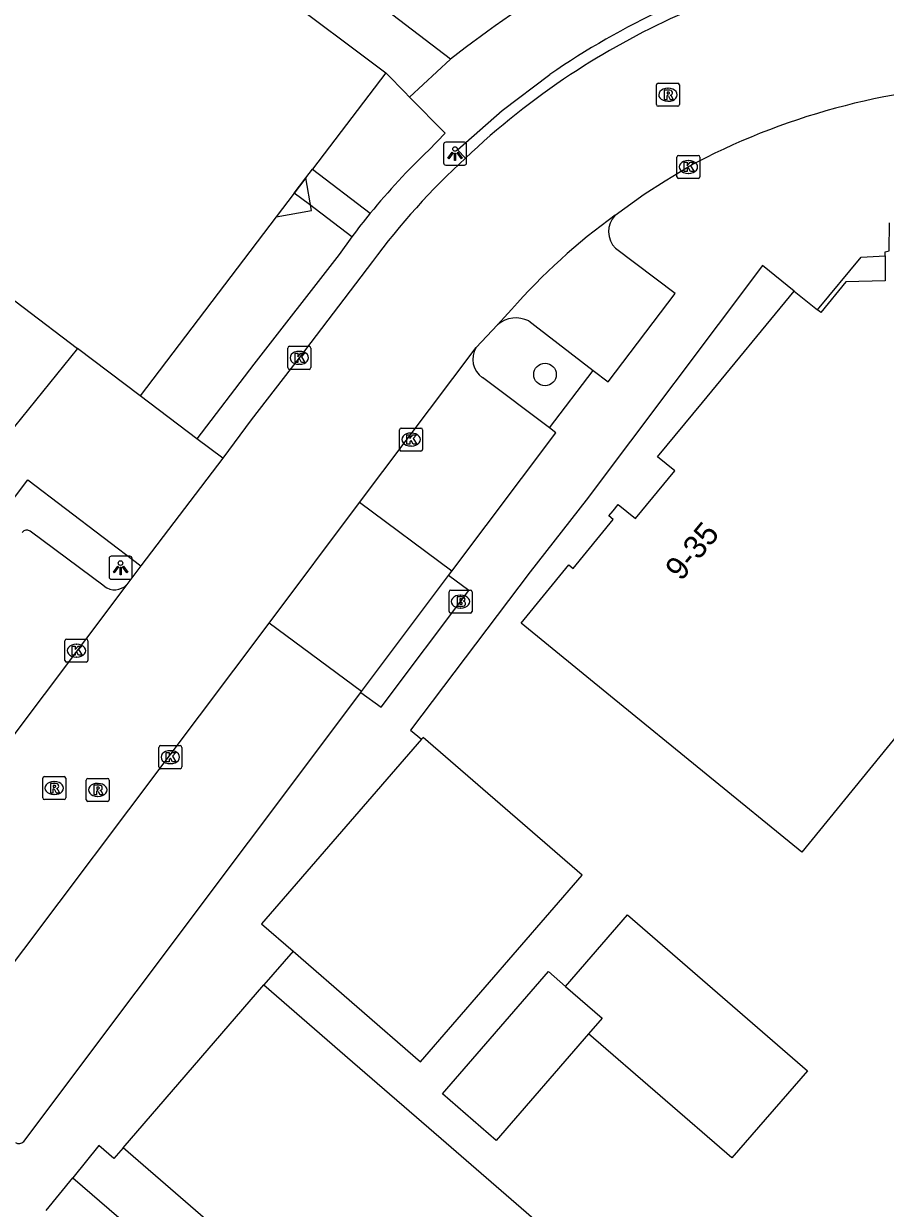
# Model space of a CAD drawing. Extents: x 161882 to 162509, y 381687 to 382379.
# Drawn here: x 162000 to 162037.4, y 382200.8 to 382252.2 of the extents above; entities that cross this region are included whole.
import ezdxf

# ---------------------------------------------------------------- set-up
doc = ezdxf.new("R2010")
doc.units = 0
for name, color, linetype in [('IMGEO_Boom', 7, 'Continuous'), ('IMGEO_Brandkraan', 7, 'Continuous'), ('IMGEO_Kolk', 7, 'Continuous'), ('IMGEO_Lichtpunt', 7, 'Continuous'), ('IMGEO_Pand', 7, 'Continuous'), ('IMGEO_Pand_nummerreeks', 7, 'Continuous'), ('IMGEO_Pand_overbouw', 7, 'Continuous'), ('IMGEO_Parkeervlak_open', 7, 'Continuous'), ('IMGEO_Rijbaan_lokaal_open', 7, 'Continuous'), ('IMGEO_Rioolput', 7, 'Continuous'), ('IMGEO_Voetpad_open', 7, 'Continuous')]:
    doc.layers.add(name, color=color, linetype=linetype)

msp = doc.modelspace()

# ---------------------------------------------------------------- linework, layer by layer
at = {"layer": 'IMGEO_Boom'}
msp.add_circle((162022.629, 382236.986), 0.489, dxfattribs=at)
at = {"layer": 'IMGEO_Brandkraan'}
for p, q in [((162018.466, 382226.715), (162018.466, 382227.567)), ((162018.541, 382227.641), (162019.393, 382227.641)), ((162018.954, 382227.421), (162018.979, 382227.421)), ((162019.467, 382227.567), (162019.467, 382226.715)), ((162018.977, 382226.861), (162018.952, 382226.861)), ((162019.393, 382226.641), (162018.541, 382226.641))]:
    msp.add_line(p, q, dxfattribs=at)
for points in [[(162018.466, 382226.715), (162018.466, 382227.567)], [(162018.541, 382227.641), (162019.393, 382227.641)], [(162018.814, 382227.341), (162018.814, 382226.941), (162019.027, 382226.941)], [(162019.045, 382227.341), (162018.814, 382227.341)], [(162018.993, 382227.26), (162018.939, 382227.26), (162018.939, 382227.184)], [(162018.939, 382227.184), (162018.992, 382227.184)], [(162019.467, 382227.567), (162019.467, 382226.715)], [(162019.001, 382227.108), (162018.939, 382227.108), (162018.939, 382227.027)], [(162018.939, 382227.027), (162019.001, 382227.027)], [(162019.393, 382226.641), (162018.541, 382226.641)]]:
    msp.add_lwpolyline(points, dxfattribs=at)
for centre, radius, start, end in [((162018.543, 382227.565), 0.0765, 91.552, 178.448), ((162018.543, 382227.565), 0.0765, 91.552, 178.448), ((162018.994, 382227.222), 0.0379, 267.8285, 90.9355), ((162019.049, 382227.196), 0.145, 59.4692, 91.5367), ((162019.074, 382227.243), 0.0922, 285.5137, 58.1501), ((162019.391, 382227.565), 0.0765, 1.552, 88.448), ((162019.391, 382227.565), 0.0765, 1.552, 88.448), ((162018.543, 382226.717), 0.0765, 181.552, 268.448), ((162018.543, 382226.717), 0.0765, 181.552, 268.448), ((162019.002, 382227.067), 0.0404, 269.8759, 90.5077), ((162019.033, 382227.192), 0.251, 268.6676, 293.5347), ((162019.079, 382227.051), 0.105, 301.3115, 78.989), ((162019.391, 382226.717), 0.0765, 271.552, 358.448), ((162019.391, 382226.717), 0.0765, 271.552, 358.448)]:
    msp.add_arc(centre, radius, start, end, dxfattribs=at)
for centre, major_axis, ratio, start_param, end_param in [((162018.953, 382227.141), (-0.387, 0.002), 0.722429, 4.712389, 7.853982), ((162018.978, 382227.141), (-0.39, 0.002), 0.717154, 1.570796, 4.712389)]:
    msp.add_ellipse(centre, major_axis=major_axis, ratio=ratio, start_param=start_param, end_param=end_param, dxfattribs=at)
at = {"layer": 'IMGEO_Kolk'}
for p, q in [((162028.346, 382245.566), (162028.346, 382246.418)), ((162028.421, 382246.492), (162029.273, 382246.492)), ((162028.834, 382246.272), (162028.859, 382246.272)), ((162029.347, 382246.418), (162029.347, 382245.566)), ((162028.857, 382245.712), (162028.832, 382245.712)), ((162029.273, 382245.492), (162028.421, 382245.492)), ((162011.473, 382237.287), (162011.473, 382238.139)), ((162011.548, 382238.213), (162012.4, 382238.213)), ((162011.961, 382237.993), (162011.986, 382237.993)), ((162012.474, 382238.139), (162012.474, 382237.287)), ((162012.4, 382237.213), (162011.548, 382237.213)), ((162011.984, 382237.433), (162011.959, 382237.433)), ((162016.322, 382233.743), (162016.322, 382234.595)), ((162016.397, 382234.669), (162017.249, 382234.669)), ((162016.81, 382234.449), (162016.835, 382234.449)), ((162017.323, 382234.595), (162017.323, 382233.743)), ((162016.833, 382233.889), (162016.808, 382233.889)), ((162017.249, 382233.669), (162016.397, 382233.669)), ((162001.809, 382224.589), (162001.809, 382225.441)), ((162001.884, 382225.515), (162002.736, 382225.515)), ((162002.297, 382225.295), (162002.322, 382225.295)), ((162002.81, 382225.441), (162002.81, 382224.589)), ((162002.32, 382224.735), (162002.295, 382224.735)), ((162002.736, 382224.515), (162001.884, 382224.515)), ((162005.882, 382219.968), (162005.882, 382220.82)), ((162005.957, 382220.894), (162006.809, 382220.894)), ((162006.37, 382220.674), (162006.395, 382220.674)), ((162006.883, 382220.82), (162006.883, 382219.968)), ((162006.393, 382220.114), (162006.368, 382220.114)), ((162006.809, 382219.894), (162005.957, 382219.894))]:
    msp.add_line(p, q, dxfattribs=at)
for points in [[(162028.346, 382245.566), (162028.346, 382246.418)], [(162028.421, 382246.492), (162029.273, 382246.492)], [(162028.667, 382246.192), (162028.79, 382246.192), (162028.79, 382246.041), (162028.92, 382246.192), (162029.084, 382246.192), (162028.938, 382246.041), (162029.091, 382245.792), (162028.939, 382245.792), (162028.854, 382245.956), (162028.79, 382245.889), (162028.79, 382245.792), (162028.667, 382245.792), (162028.667, 382246.192)], [(162029.347, 382246.418), (162029.347, 382245.566)], [(162029.273, 382245.492), (162028.421, 382245.492)], [(162011.473, 382237.287), (162011.473, 382238.139)], [(162011.548, 382238.213), (162012.4, 382238.213)], [(162012.474, 382238.139), (162012.474, 382237.287)], [(162011.794, 382237.913), (162011.917, 382237.913), (162011.917, 382237.762), (162012.047, 382237.913), (162012.211, 382237.913), (162012.065, 382237.762), (162012.218, 382237.513), (162012.066, 382237.513), (162011.981, 382237.677), (162011.917, 382237.61), (162011.917, 382237.513), (162011.794, 382237.513), (162011.794, 382237.913)], [(162012.4, 382237.213), (162011.548, 382237.213)], [(162016.322, 382233.743), (162016.322, 382234.595)], [(162016.397, 382234.669), (162017.249, 382234.669)], [(162017.323, 382234.595), (162017.323, 382233.743)], [(162016.643, 382234.369), (162016.766, 382234.369), (162016.766, 382234.218), (162016.896, 382234.369), (162017.06, 382234.369), (162016.914, 382234.218), (162017.067, 382233.969), (162016.915, 382233.969), (162016.83, 382234.133), (162016.766, 382234.066), (162016.766, 382233.969), (162016.643, 382233.969), (162016.643, 382234.369)], [(162017.249, 382233.669), (162016.397, 382233.669)], [(162001.809, 382224.589), (162001.809, 382225.441)], [(162001.884, 382225.515), (162002.736, 382225.515)], [(162002.13, 382225.215), (162002.253, 382225.215), (162002.253, 382225.064), (162002.383, 382225.215), (162002.547, 382225.215), (162002.401, 382225.064), (162002.554, 382224.815), (162002.402, 382224.815), (162002.317, 382224.979), (162002.253, 382224.912), (162002.253, 382224.815), (162002.13, 382224.815), (162002.13, 382225.215)], [(162002.81, 382225.441), (162002.81, 382224.589)], [(162002.736, 382224.515), (162001.884, 382224.515)], [(162005.882, 382219.968), (162005.882, 382220.82)], [(162005.957, 382220.894), (162006.809, 382220.894)], [(162006.203, 382220.594), (162006.326, 382220.594), (162006.326, 382220.443), (162006.456, 382220.594), (162006.62, 382220.594), (162006.474, 382220.443), (162006.627, 382220.194), (162006.475, 382220.194), (162006.39, 382220.358), (162006.326, 382220.291), (162006.326, 382220.194), (162006.203, 382220.194), (162006.203, 382220.594)], [(162006.883, 382220.82), (162006.883, 382219.968)], [(162006.809, 382219.894), (162005.957, 382219.894)]]:
    msp.add_lwpolyline(points, dxfattribs=at)
for centre, start, end in [((162028.423, 382246.416), 91.552, 178.448), ((162028.423, 382246.416), 91.552, 178.448), ((162029.271, 382246.416), 1.552, 88.448), ((162029.271, 382246.416), 1.552, 88.448), ((162028.423, 382245.568), 181.552, 268.448), ((162028.423, 382245.568), 181.552, 268.448), ((162029.271, 382245.568), 271.552, 358.448), ((162029.271, 382245.568), 271.552, 358.448), ((162011.55, 382238.137), 91.552, 178.448), ((162011.55, 382238.137), 91.552, 178.448), ((162012.398, 382238.137), 1.552, 88.448), ((162012.398, 382238.137), 1.552, 88.448), ((162011.55, 382237.289), 181.552, 268.448), ((162011.55, 382237.289), 181.552, 268.448), ((162012.398, 382237.289), 271.552, 358.448), ((162012.398, 382237.289), 271.552, 358.448), ((162016.399, 382234.593), 91.552, 178.448), ((162016.399, 382234.593), 91.552, 178.448), ((162017.247, 382234.593), 1.552, 88.448), ((162017.247, 382234.593), 1.552, 88.448), ((162016.399, 382233.745), 181.552, 268.448), ((162016.399, 382233.745), 181.552, 268.448), ((162017.247, 382233.745), 271.552, 358.448), ((162017.247, 382233.745), 271.552, 358.448), ((162001.886, 382225.439), 91.552, 178.448), ((162001.886, 382225.439), 91.552, 178.448), ((162002.734, 382225.439), 1.552, 88.448), ((162002.734, 382225.439), 1.552, 88.448), ((162001.886, 382224.591), 181.552, 268.448), ((162001.886, 382224.591), 181.552, 268.448), ((162002.734, 382224.591), 271.552, 358.448), ((162002.734, 382224.591), 271.552, 358.448), ((162005.959, 382220.818), 91.552, 178.448), ((162005.959, 382220.818), 91.552, 178.448), ((162006.807, 382220.818), 1.552, 88.448), ((162006.807, 382220.818), 1.552, 88.448), ((162005.959, 382219.97), 181.552, 268.448), ((162005.959, 382219.97), 181.552, 268.448), ((162006.807, 382219.97), 271.552, 358.448), ((162006.807, 382219.97), 271.552, 358.448)]:
    msp.add_arc(centre, 0.0765, start, end, dxfattribs=at)
for centre, major_axis, ratio, start_param, end_param in [((162028.833, 382245.992), (-0.387, 0.002), 0.722429, 4.712389, 7.853982), ((162028.858, 382245.992), (-0.39, 0.002), 0.717154, 1.570796, 4.712389), ((162011.96, 382237.713), (-0.387, 0.002), 0.722429, 4.712389, 7.853982), ((162011.985, 382237.713), (-0.39, 0.002), 0.717154, 1.570796, 4.712389), ((162016.809, 382234.169), (-0.387, 0.002), 0.722429, 4.712389, 7.853982), ((162016.834, 382234.169), (-0.39, 0.002), 0.717154, 1.570796, 4.712389), ((162002.296, 382225.015), (-0.387, 0.002), 0.722429, 4.712389, 7.853982), ((162002.321, 382225.015), (-0.39, 0.002), 0.717154, 1.570796, 4.712389), ((162006.369, 382220.394), (-0.387, 0.002), 0.722429, 4.712389, 7.853982), ((162006.394, 382220.394), (-0.39, 0.002), 0.717154, 1.570796, 4.712389)]:
    msp.add_ellipse(centre, major_axis=major_axis, ratio=ratio, start_param=start_param, end_param=end_param, dxfattribs=at)
at = {"layer": 'IMGEO_Lichtpunt'}
for p, q in [((162018.231, 382246.971), (162018.231, 382246.164)), ((162018.231, 382246.971), (162018.231, 382246.164)), ((162019.133, 382247.066), (162018.325, 382247.066)), ((162019.133, 382247.066), (162018.325, 382247.066)), ((162019.227, 382246.164), (162019.227, 382246.971)), ((162019.227, 382246.164), (162019.227, 382246.971)), ((162018.325, 382246.07), (162019.133, 382246.07)), ((162018.325, 382246.07), (162019.133, 382246.07)), ((162003.724, 382229.014), (162003.724, 382228.207)), ((162003.724, 382229.014), (162003.724, 382228.207)), ((162004.626, 382229.109), (162003.818, 382229.109)), ((162004.626, 382229.109), (162003.818, 382229.109)), ((162004.72, 382228.207), (162004.72, 382229.014)), ((162004.72, 382228.207), (162004.72, 382229.014)), ((162003.818, 382228.113), (162004.626, 382228.113)), ((162003.818, 382228.113), (162004.626, 382228.113))]:
    msp.add_line(p, q, dxfattribs=at)
for points in [[(162018.605, 382246.635), (162018.644, 382246.607), (162018.456, 382246.345), (162018.418, 382246.372), (162018.605, 382246.635)], [(162018.707, 382246.587), (162018.754, 382246.587), (162018.754, 382246.265), (162018.707, 382246.265), (162018.707, 382246.587)], [(162018.817, 382246.607), (162018.855, 382246.634), (162019.042, 382246.372), (162019.003, 382246.344), (162018.817, 382246.607)], [(162004.098, 382228.678), (162004.137, 382228.65), (162003.949, 382228.388), (162003.911, 382228.415), (162004.098, 382228.678)], [(162004.2, 382228.63), (162004.247, 382228.63), (162004.247, 382228.308), (162004.2, 382228.308), (162004.2, 382228.63)], [(162004.31, 382228.65), (162004.348, 382228.677), (162004.535, 382228.415), (162004.496, 382228.387), (162004.31, 382228.65)]]:
    msp.add_lwpolyline(points, dxfattribs=at)
for centre in [(162018.73, 382246.769), (162004.223, 382228.812)]:
    msp.add_circle(centre, 0.0994, dxfattribs=at)
for centre, start, end in [((162018.325, 382246.971), 90, 180), ((162018.325, 382246.971), 90, 180), ((162019.133, 382246.971), 0, 90), ((162019.133, 382246.971), 0, 90), ((162018.325, 382246.164), 180, 270), ((162018.325, 382246.164), 180, 270), ((162019.133, 382246.164), 270, 0), ((162019.133, 382246.164), 270, 360), ((162003.818, 382229.014), 90, 180), ((162003.818, 382229.014), 90, 180), ((162004.626, 382229.014), 0, 90), ((162004.626, 382229.014), 0, 90), ((162003.818, 382228.207), 180, 270), ((162003.818, 382228.207), 180, 270), ((162004.626, 382228.207), 270, 0), ((162004.626, 382228.207), 270, 360)]:
    msp.add_arc(centre, 0.0946, start, end, dxfattribs=at)
at = {"layer": 'IMGEO_Pand'}
for points in [[(162011.059, 382253.58), (162015.722, 382250.073)], [(162015.722, 382250.073), (162012.544, 382245.889)], [(161990.561, 382247.065), (162000, 382239.908), (162002.356, 382238.121)], [(162011.758, 382244.854), (162012.261, 382245.517), (162012.544, 382245.889)], [(162011.758, 382244.854), (162010.978, 382243.828), (162005.076, 382236.059)], [(162037.377, 382242.139), (162037.376, 382242.31), (162037.558, 382242.348), (162037.565, 382243.563)], [(162037.377, 382242.139), (162037.383, 382241.049), (162035.673, 382241.016), (162034.586, 382239.676), (162034.44, 382239.794)], [(162040.524, 382224.57), (162033.762, 382216.278), (162025.47, 382223.04), (162021.595, 382226.2), (162023.659, 382228.731), (162023.852, 382228.572), (162025.591, 382230.7), (162025.396, 382230.856), (162025.578, 382231.083), (162025.799, 382231.359), (162026.551, 382230.746), (162028.26, 382232.806), (162027.511, 382233.423), (162029.455, 382235.782), (162033.432, 382240.608)], [(162033.432, 382240.608), (162034.44, 382239.794)], [(162005.076, 382236.059), (162002.356, 382238.121)], [(162017.27, 382221.17), (162010.341, 382213.16), (162011.707, 382211.975)], [(162011.707, 382211.975), (162017.234, 382207.181), (162024.234, 382215.271), (162017.341, 382221.25), (162017.27, 382221.17)], [(162023.519, 382210.448), (162026.213, 382213.555), (162034.009, 382206.793), (162030.737, 382203.02), (162024.516, 382208.4)], [(162024.516, 382208.4), (162020.512, 382203.771), (162018.182, 382205.787), (162022.773, 382211.095), (162023.519, 382210.448)], [(162010.443, 382210.514), (162014.282, 382207.186), (162018.121, 382203.859), (162041.023, 382184.008), (162041.152, 382183.891), (162035.04, 382176.852), (162004.335, 382203.455)], [(162004.335, 382203.455), (162010.443, 382210.514)], [(162023.519, 382210.448), (162025.101, 382209.076), (162024.516, 382208.4)]]:
    msp.add_lwpolyline(points, dxfattribs=at)
at = {"layer": 'IMGEO_Pand_overbouw'}
msp.add_lwpolyline([(162012.505, 382244.105), (162012.261, 382245.517), (162010.978, 382243.828)], close=True, dxfattribs=at)
at = {"layer": 'IMGEO_Parkeervlak_open'}
for points in [[(162021.928, 382239.311), (162022.186, 382239.112), (162024.718, 382237.167)], [(162022.821, 382234.676), (162019.914, 382236.853)], [(162003.509, 382227.805), (162000.298, 382230.196)]]:
    msp.add_lwpolyline(points, dxfattribs=at)
for centre, radius, start, end in [((162021.373, 382238.213), 1.23, 63.1997, 130.4558), ((162020.461, 382237.646), 0.964, 147.6505, 235.4067), ((162000.154, 382229.984), 0.257, 55.9195, 142.4156), ((162003.961, 382228.396), 0.744, 232.5642, 315.6814)]:
    msp.add_arc(centre, radius, start, end, dxfattribs=at)
at = {"layer": 'IMGEO_Rijbaan_lokaal_open'}
for points in [[(162018.527, 382250.66), (162010.479, 382256.829), (162002.346, 382262.989)], [(162025.67, 382243.894), (162026.924, 382244.813), (162027.846, 382245.385), (162028.842, 382245.993)], [(162015.142, 382241.884), (162011.971, 382237.712), (162009.881, 382235.025), (162008.661, 382233.367)], [(162020.575, 382239.149), (162021.178, 382239.811)], [(162019.647, 382238.162), (162020.575, 382239.149)], [(162014.591, 382231.432), (162019.647, 382238.162)], [(162008.661, 382233.367), (162005.109, 382228.696)], [(162010.665, 382226.206), (162014.591, 382231.432)], [(162018.589, 382228.455), (162014.591, 382231.432)], [(162005.109, 382228.696), (162004.494, 382227.876)], [(162014.673, 382223.238), (162018.451, 382228.271)], [(162018.451, 382228.271), (162018.589, 382228.455)], [(162004.494, 382227.876), (161990.138, 382208.807)], [(161995.464, 382205.989), (162010.665, 382226.206)], [(162014.673, 382223.238), (162010.665, 382226.206)]]:
    msp.add_lwpolyline(points, dxfattribs=at)
for centre, radius, start, end in [((162048.55, 382212.364), 48.661, 120.4733, 128.0958), ((162041.874, 382222.542), 32.905, 105.0443, 123.4424), ((162041.887, 382222.526), 32.926, 123.4453, 133.6105), ((162043.066, 382219.614), 29.969, 92.0052, 118.3335), ((162040.153, 382223.43), 31.082, 132.4448, 143.5779), ((162041.359, 382222.121), 26.836, 125.7753, 138.7632)]:
    msp.add_arc(centre, radius, start, end, dxfattribs=at)
at = {"layer": 'IMGEO_Rioolput'}
for p, q in [((162027.459, 382248.696), (162027.459, 382249.548)), ((162027.534, 382249.622), (162028.386, 382249.622)), ((162027.947, 382249.402), (162027.972, 382249.402)), ((162028.46, 382249.548), (162028.46, 382248.696)), ((162027.97, 382248.842), (162027.945, 382248.842)), ((162028.386, 382248.622), (162027.534, 382248.622)), ((162000.846, 382218.627), (162000.846, 382219.479)), ((162000.921, 382219.553), (162001.773, 382219.553)), ((162001.847, 382219.479), (162001.847, 382218.627)), ((162002.809, 382219.475), (162003.661, 382219.475)), ((162001.334, 382219.333), (162001.359, 382219.333)), ((162002.734, 382218.549), (162002.734, 382219.401)), ((162003.222, 382219.255), (162003.247, 382219.255)), ((162003.735, 382219.401), (162003.735, 382218.549)), ((162001.773, 382218.553), (162000.921, 382218.553)), ((162001.357, 382218.773), (162001.332, 382218.773)), ((162003.661, 382218.475), (162002.809, 382218.475)), ((162003.245, 382218.695), (162003.22, 382218.695))]:
    msp.add_line(p, q, dxfattribs=at)
for points in [[(162027.459, 382248.696), (162027.459, 382249.548)], [(162027.534, 382249.622), (162028.386, 382249.622)], [(162028.048, 382249.32), (162027.796, 382249.322), (162027.796, 382248.922)], [(162028.46, 382249.548), (162028.46, 382248.696)], [(162027.796, 382248.922), (162027.92, 382248.922), (162027.92, 382249.084), (162027.931, 382249.084)], [(162027.974, 382249.241), (162027.92, 382249.241), (162027.92, 382249.16)], [(162027.92, 382249.16), (162027.972, 382249.16)], [(162027.978, 382249.055), (162028.049, 382248.922), (162028.189, 382248.922), (162028.124, 382249.048)], [(162028.386, 382248.622), (162027.534, 382248.622)], [(162000.846, 382218.627), (162000.846, 382219.479)], [(162000.921, 382219.553), (162001.773, 382219.553)], [(162001.847, 382219.479), (162001.847, 382218.627)], [(162002.809, 382219.475), (162003.661, 382219.475)], [(162001.435, 382219.251), (162001.183, 382219.253), (162001.183, 382218.853)], [(162001.183, 382218.853), (162001.307, 382218.853), (162001.307, 382219.015), (162001.318, 382219.015)], [(162001.361, 382219.172), (162001.307, 382219.172), (162001.307, 382219.091)], [(162001.307, 382219.091), (162001.359, 382219.091)], [(162001.365, 382218.986), (162001.436, 382218.853), (162001.576, 382218.853), (162001.511, 382218.979)], [(162002.734, 382218.549), (162002.734, 382219.401)], [(162003.323, 382219.173), (162003.071, 382219.175), (162003.071, 382218.775)], [(162003.249, 382219.094), (162003.195, 382219.094), (162003.195, 382219.013)], [(162003.195, 382219.013), (162003.247, 382219.013)], [(162003.735, 382219.401), (162003.735, 382218.549)], [(162001.773, 382218.553), (162000.921, 382218.553)], [(162003.661, 382218.475), (162002.809, 382218.475)], [(162003.071, 382218.775), (162003.195, 382218.775), (162003.195, 382218.937), (162003.206, 382218.937)], [(162003.253, 382218.908), (162003.324, 382218.775), (162003.464, 382218.775), (162003.399, 382218.901)]]:
    msp.add_lwpolyline(points, dxfattribs=at)
for centre, radius, start, end in [((162027.536, 382249.546), 0.0765, 91.552, 178.448), ((162027.536, 382249.546), 0.0765, 91.552, 178.448), ((162028.047, 382249.21), 0.109, 350.3612, 89.416), ((162028.384, 382249.546), 0.0765, 1.552, 88.448), ((162028.384, 382249.546), 0.0765, 1.552, 88.448), ((162027.93, 382249.031), 0.0533, 26.0293, 88.6989), ((162027.956, 382249.349), 0.19, 274.7715, 282.9687), ((162027.98, 382249.145), 0.0964, 77.0061, 93.1865), ((162027.994, 382249.202), 0.0378, 276.6634, 79.6772), ((162028.045, 382249.21), 0.112, 277.5842, 350.9817), ((162028.029, 382248.995), 0.108, 29.5134, 73.7905), ((162027.536, 382248.698), 0.0765, 181.552, 268.448), ((162027.536, 382248.698), 0.0765, 181.552, 268.448), ((162028.384, 382248.698), 0.0765, 271.552, 358.448), ((162028.384, 382248.698), 0.0765, 271.552, 358.448), ((162000.923, 382219.477), 0.0765, 91.552, 178.448), ((162000.923, 382219.477), 0.0765, 91.552, 178.448), ((162001.771, 382219.477), 0.0765, 1.552, 88.448), ((162001.771, 382219.477), 0.0765, 1.552, 88.448), ((162002.811, 382219.399), 0.0765, 91.552, 178.448), ((162002.811, 382219.399), 0.0765, 91.552, 178.448), ((162003.659, 382219.399), 0.0765, 1.552, 88.448), ((162003.659, 382219.399), 0.0765, 1.552, 88.448), ((162001.317, 382218.962), 0.0533, 26.0293, 88.6989), ((162001.343, 382219.28), 0.19, 274.7715, 282.9687), ((162001.367, 382219.076), 0.0964, 77.0061, 93.1865), ((162001.381, 382219.133), 0.0378, 276.6634, 79.6772), ((162001.434, 382219.141), 0.109, 350.3612, 89.416), ((162001.432, 382219.141), 0.112, 277.5842, 350.9817), ((162001.416, 382218.926), 0.108, 29.5134, 73.7905), ((162003.231, 382219.202), 0.19, 274.7715, 282.9687), ((162003.255, 382218.998), 0.0964, 77.0061, 93.1865), ((162003.269, 382219.055), 0.0378, 276.6634, 79.6772), ((162003.322, 382219.063), 0.109, 350.3612, 89.416), ((162003.32, 382219.063), 0.112, 277.5842, 350.9817), ((162000.923, 382218.629), 0.0765, 181.552, 268.448), ((162000.923, 382218.629), 0.0765, 181.552, 268.448), ((162001.771, 382218.629), 0.0765, 271.552, 358.448), ((162001.771, 382218.629), 0.0765, 271.552, 358.448), ((162002.811, 382218.551), 0.0765, 181.552, 268.448), ((162002.811, 382218.551), 0.0765, 181.552, 268.448), ((162003.205, 382218.884), 0.0533, 26.0293, 88.6989), ((162003.304, 382218.848), 0.108, 29.5134, 73.7905), ((162003.659, 382218.551), 0.0765, 271.552, 358.448), ((162003.659, 382218.551), 0.0765, 271.552, 358.448)]:
    msp.add_arc(centre, radius, start, end, dxfattribs=at)
for centre, major_axis, ratio, start_param, end_param in [((162027.946, 382249.122), (-0.387, 0.002), 0.722429, 4.712389, 7.853982), ((162027.971, 382249.122), (-0.39, 0.002), 0.717154, 1.570796, 4.712389), ((162001.333, 382219.053), (-0.387, 0.002), 0.722429, 4.712389, 7.853982), ((162001.358, 382219.053), (-0.39, 0.002), 0.717154, 1.570796, 4.712389), ((162003.221, 382218.975), (-0.387, 0.002), 0.722429, 4.712389, 7.853982), ((162003.246, 382218.975), (-0.39, 0.002), 0.717154, 1.570796, 4.712389)]:
    msp.add_ellipse(centre, major_axis=major_axis, ratio=ratio, start_param=start_param, end_param=end_param, dxfattribs=at)
at = {"layer": 'IMGEO_Voetpad_open'}
for points in [[(162016.754, 382249.024), (162018.527, 382250.66)], [(162015.722, 382250.073), (162015.794, 382250), (162016.53, 382249.251), (162016.754, 382249.024)], [(162019.176, 382246.366), (162018.828, 382246.737), (162020.77, 382248.446), (162022.838, 382250)], [(162017.588, 382246.723), (162018.3, 382247.451), (162016.754, 382249.024)], [(162012.544, 382245.889), (162015.052, 382243.983)], [(162014.251, 382242.96), (162012.413, 382244.356), (162011.758, 382244.854)], [(162014.251, 382242.96), (162013.698, 382242.196), (162010.005, 382237.444), (162007.53, 382234.195)], [(162024.718, 382237.167), (162025.361, 382236.673), (162028.273, 382240.499), (162025.692, 382242.462)], [(162034.44, 382239.794), (162036.342, 382242.085), (162037.377, 382242.139)], [(162033.432, 382240.608), (162032.066, 382241.723), (162024.409, 382231.541), (162021.982, 382228.43), (162016.798, 382221.562), (162017.27, 382221.17)], [(162002.356, 382238.121), (161998.699, 382233.61), (161986.724, 382217.648)], [(162022.821, 382234.676), (162024.718, 382237.167)], [(162007.53, 382234.195), (162005.076, 382236.059)], [(162018.589, 382228.455), (162023.101, 382234.466), (162022.821, 382234.676)], [(162008.661, 382233.367), (162007.53, 382234.195)], [(161988.573, 382208.526), (161984.491, 382211.627), (162000.199, 382232.429), (162005.109, 382228.696)], [(162014.645, 382223.2), (162015.518, 382222.556), (162019.33, 382227.626), (162018.451, 382228.271)], [(162000.023, 382203.725), (162014.645, 382223.2)], [(162014.645, 382223.2), (162014.673, 382223.238)], [(162011.707, 382211.975), (162010.443, 382210.514)], [(162004.335, 382203.455), (162003.926, 382202.983), (162003.275, 382203.547), (162002.15, 382202.152)], [(162001.003, 382200.728), (162002.15, 382202.152)], [(162002.15, 382202.152), (162007.715, 382197.353), (162034.901, 382173.742), (162058.69, 382153.142), (162067.845, 382145.177), (162076.705, 382137.459), (162080.965, 382142.814), (162080.908, 382142.859)]]:
    msp.add_lwpolyline(points, dxfattribs=at)
for centre, radius, start, end in [((162041.879, 382222.494), 33.453, 105.0166, 124.6927), ((162038.609, 382224.723), 30.428, 133.6971, 140.7315), ((162038.034, 382225.163), 29.704, 140.6862, 143.1925), ((162026.409, 382243.189), 1.021, 136.3686, 225.3918), ((161999.83, 382203.883), 0.249, 231.1737, 320.605)]:
    msp.add_arc(centre, radius, start, end, dxfattribs=at)

# ---------------------------------------------------------------- texts
at = {"layer": 'IMGEO_Pand_nummerreeks'}
msp.add_text('9-35', height=1, rotation=50.3205, dxfattribs=at).set_placement((162028.529, 382227.993))

doc.saveas('drawing.dxf')
